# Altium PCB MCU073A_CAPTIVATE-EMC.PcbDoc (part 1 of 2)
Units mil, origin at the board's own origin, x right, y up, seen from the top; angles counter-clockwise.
Board outline 5374.02 x 3444.88 mil, 2 copper layers (Top Layer, Bottom Layer), stack 62 mil thick; 125 components, 86 nets, 448 pads, 154 vias.
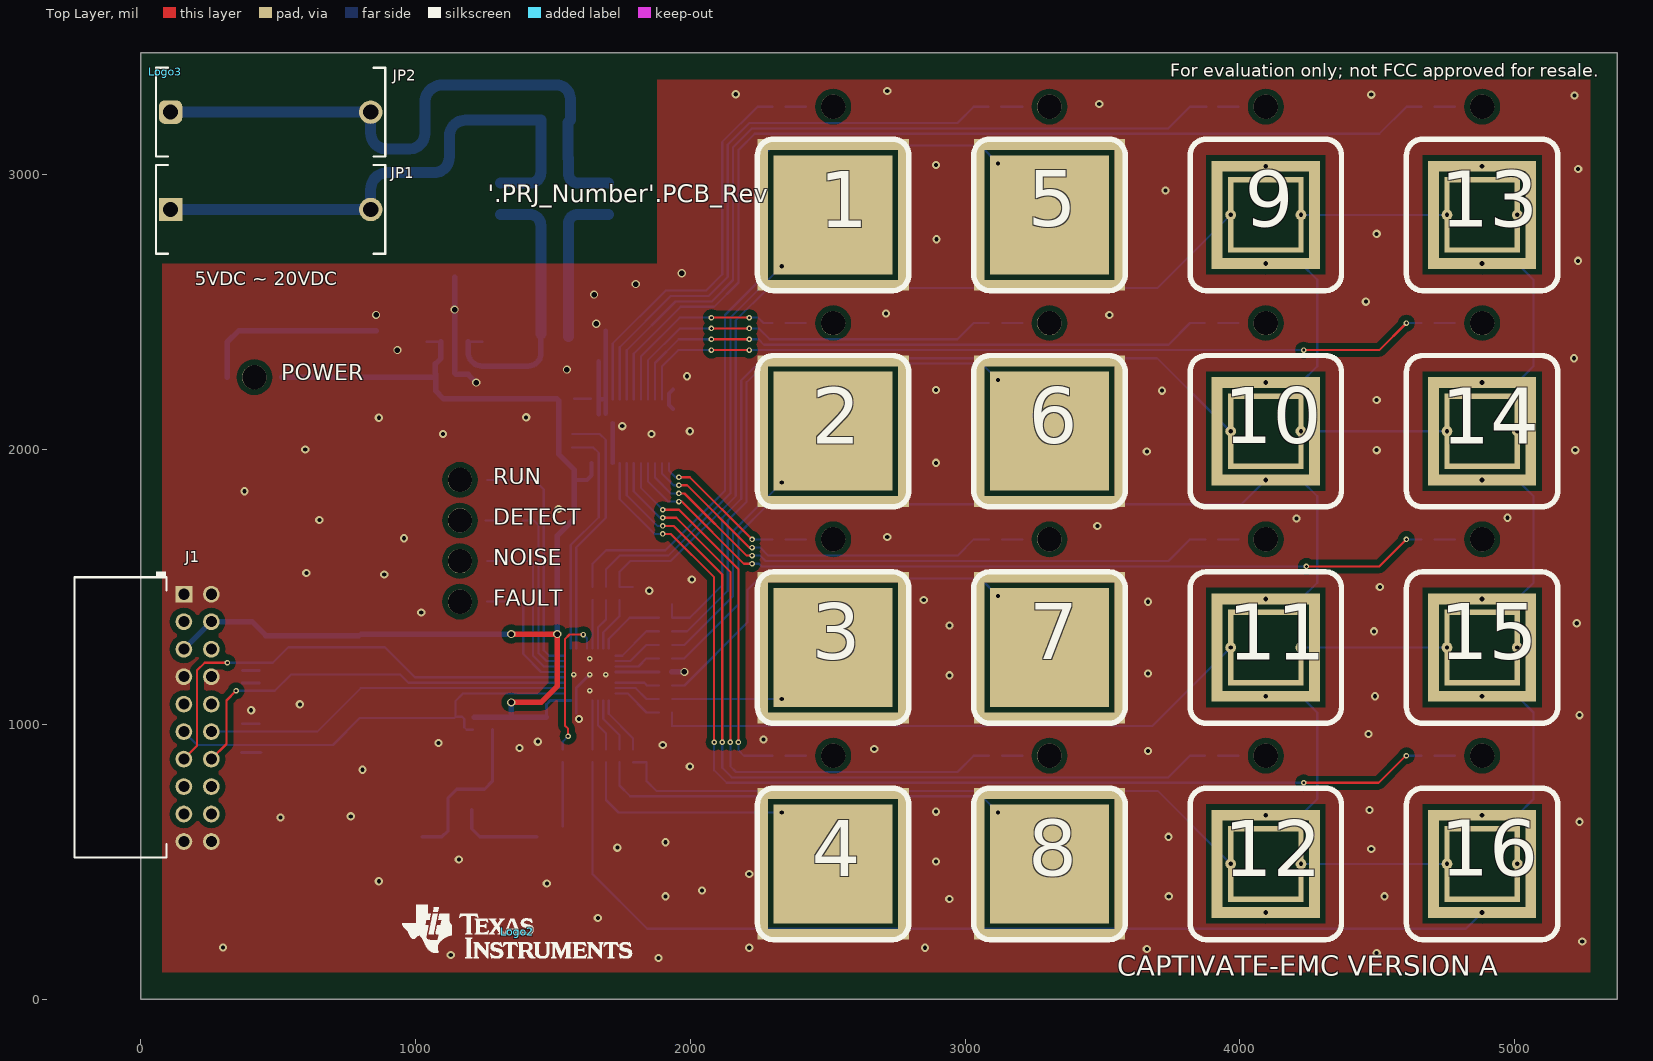
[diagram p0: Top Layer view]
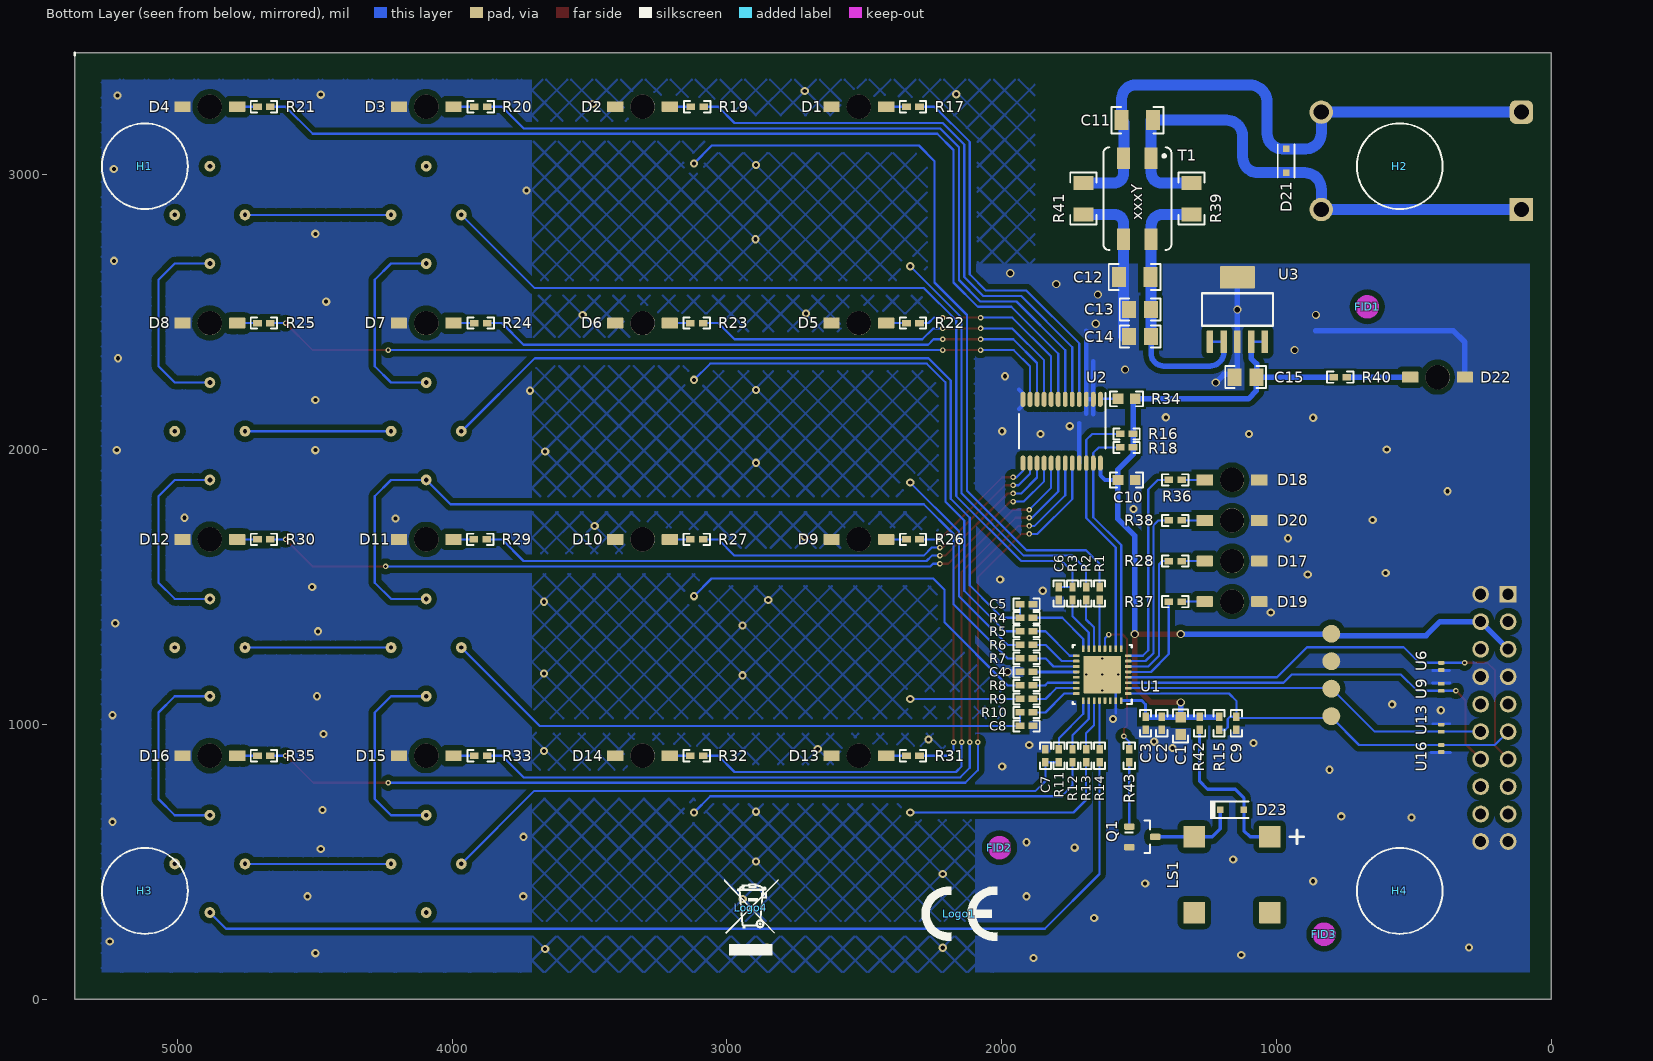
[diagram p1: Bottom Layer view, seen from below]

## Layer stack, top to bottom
Top Solder: solder mask 0.4, Solder Resist, Dk 3.5
Top Layer: signal copper 1.4
Dielectric1: core 59.2, FR-4, Dk 4.8
Bottom Layer: signal copper 1.4
Bottom Solder: solder mask 0.4, Solder Resist, Dk 3.5

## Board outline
0,0 0,3444.88 5374.02,3444.88 5374.02,0

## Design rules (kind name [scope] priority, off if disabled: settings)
AcuteAngle [All] p1: minimum=4.50000000000000E+0001 checktracksonly=FALSE
AssemblyTestPointUsage [All] p1: valid=2
BoardOutlineClearance BoardOutlineClearance_MountingHoles [OnCopper and InComponentClass('Mounting Holes')] p1: gap=39.37 ignorepadtopadclearanceinfootprint=FALSE
BoardOutlineClearance BoardOutlineClearance_Poly [OnCopper and IsPoly] p2: gap=25 ignorepadtopadclearanceinfootprint=FALSE
BoardOutlineClearance [OnCopper and Not InComponentClass('Logo') and not InComponentClass('FiducialMark') and not InRegion(1000,500,4000,800) and not InPoly] p3: gap=50 ignorepadtopadclearanceinfootprint=FALSE
Clearance Clearance_Keepouts [((IsTrack Or IsArc) And Not InPoly) And IsFree and IsKeepOut vs ((IsTrack Or IsArc) And Not InPoly) And IsFree and IsKeepOut] p1: gap=0 ignorepadtopadclearanceinfootprint=FALSE
Clearance Clearance_Poly [InPolygon] p2: gap=20 ignorepadtopadclearanceinfootprint=TRUE
Clearance Clearance_FiducialMark [IsKeepOut and InComponentClass('FiducialMark') vs IsPad and InComponentClass('FiducialMark')] p3: gap=0 ignorepadtopadclearanceinfootprint=FALSE
Clearance [All] p4: gap=7.87 ignorepadtopadclearanceinfootprint=TRUE
ComponentClearance ComponentClearance_MountingHoles_FiducialMarks [InComponentClass('Mounting Holes') vs InComponentClass('FiducialMark')] p1: gap=50 collisioncheckmode=3 verticalgap=10 showdistances=FALSE
ComponentClearance ComponentClearance_Overlay [HasFootprint('CAPTIVATE-EMC-OVERLAY-PMMA')] p2: gap=0 collisioncheckmode=3 verticalgap=0 showdistances=FALSE
ComponentClearance ComponentClearance_Shunt [InComponentClass('Header') vs InComponentClass('Shunt')] p3: gap=0 collisioncheckmode=3 verticalgap=0 showdistances=FALSE
ComponentClearance ComponentClearance_Logo [InComponentClass('Logo')] p4: gap=50 collisioncheckmode=3 verticalgap=10 showdistances=FALSE
ComponentClearance ComponentClearance_ScrewToNut [(HasFootprint('NY PMS 440 0025 PH')) vs (HasFootprint('Keystone_1902C'))] p5: gap=5 collisioncheckmode=3 verticalgap=10 showdistances=FALSE
ComponentClearance ComponentClearance_MountingHoles [InComponentClass('Mounting Holes')] p6: gap=250 collisioncheckmode=3 verticalgap=100000 showdistances=FALSE
ComponentClearance ComponentClearance_SmallPassives [HasFootprint('0201*') or HasFootprint('0402*') or HasFootprint('0508') or HasFootprint('0603*') or HasFootprint('0612') or HasFootprint('0805*') or HasFootprint('0815*') or HasFootprint('0830*') or HasFootprint('1206*') or HasFootprint('1210*') or HasFootprint('1808*') or HasFootprint('1812*') or HasFootprint('1825*') or HasFootprint('2010*') or HasFootprint('2220*') or HasFootprint('2225*') or HasFootprint('2512*') or HasFootprint('2728*') or HasFootprint('3518*') vs HasFootprint('0201*') or HasFootprint('0402*') or HasFootprint('0508') or HasFootprint('0603*') or HasFootprint('0612') or HasFootprint('0805*') or HasFootprint('0815*') or HasFootprint('0830*') or HasFootprint('1206*') or HasFootprint('1210*') or HasFootprint('1808*') or HasFootprint('1812*') or HasFootprint('1825*') or HasFootprint('2010*') or HasFootprint('2220*') or HasFootprint('2225*') or HasFootprint('2512*') or HasFootprint('2728*') or HasFootprint('3518*')] p7: gap=14.96 collisioncheckmode=3 verticalgap=10 showdistances=FALSE
ComponentClearance ComponentClearance_THtoSMT [IsThruComponent vs IsSMTComponent] p8: gap=40 collisioncheckmode=3 verticalgap=30 showdistances=FALSE
ComponentClearance ComponentClearance_THtoTH [IsThruComponent vs IsThruComponent] p9: gap=30 collisioncheckmode=3 verticalgap=30 showdistances=FALSE
ComponentClearance [All] p10: gap=30 collisioncheckmode=3 verticalgap=10 showdistances=FALSE
DiffPairsRouting [All] p1: maxlimit=100 minlimit=10 mostfreqgap=10 toplayer_minwidth=15 toplayer_maxwidth=15 toplayer_prefwidth=15 bottomlayer_minwidth=15 bottomlayer_maxwidth=15 bottomlayer_prefwidth=15 maxuncoupledlength=1000
FabricationTestPointUsage TestPointUsage [All] p1: valid=2 allowmultiple=FALSE
FabricationTestpoint Testpoint [All] p1: side=3 testpointundercomponent=TRUE minsize=40 maxsize=100 preferedsize=60 minholesize=0 maxholesize=40 preferedholesize=32 testpointgrid=1 allowsidetop=TRUE allowsidebottom=TRUE usegrid=TRUE gridtolerance=0.01
FanoutControl Fanout_LCC [IsLCC] p1: bgadir=Out bgaviamode=Centered fanoutstyle=Auto fanoutdirection=Alternating viagrid=1 // Fanout_LCC (Default Rule)
FanoutControl Fanout_BGA [IsBGA] p2: bgadir=Out bgaviamode=Centered fanoutstyle=Auto fanoutdirection=Alternating viagrid=1 // Fanout_BGA (Default Rule)
FanoutControl Fanout_Default [All] p4: bgadir=Out bgaviamode=Centered fanoutstyle=Auto fanoutdirection=Alternating viagrid=1 // Fanout_Default (Default Rule)
FanoutControl Fanout_Small [(CompPinCount < 5)] p5: bgadir=Out bgaviamode=Centered fanoutstyle=Auto fanoutdirection=OutThenIn viagrid=1 // Fanout_Small (Default Rule)
HoleSize [All] p1: absolutevalues=TRUE maxlimit=251 minlimit=7.87 maxpercent=80.000 minpercent=20.000
MinimumAnnularRing MinimumAnnularRing_ThermalPadVias [IsVia and InAnyComponent] p1: minimumring=5.91
MinimumAnnularRing [All] p2: minimumring=5
MinimumSolderMaskSliver MinimumSolderMaskSliver_Logo [InComponentClass('Logo') vs InComponentClass('Logo')] p1: minsoldermaskwidth=0.7
MinimumSolderMaskSliver [All] p2: minsoldermaskwidth=3.94
PlaneConnect [All] p1: planeconnectstyle=Direct reliefexpansion=10 reliefentries=4 reliefconductorwidth=10 reliefairgap=10
PolygonConnect [All] p1: connectstyle=Direct reliefconductorwidth=10 reliefentries=4 polygonreliefangle="90 Angle" airgapwidth=10
RoutingVias ThermalPadVias [IsVia and InAnyComponent] p1: holewidth=7.87 width=19.68 viastyle="Through Hole" minholewidth=7.87 minwidth=19.68 maxholewidth=12.99 maxwidth=23.62
RoutingVias [All] p2: holewidth=16 width=34 viastyle="Through Hole" minholewidth=7.87 minwidth=20 maxholewidth=40 maxwidth=65
SilkToBoardRegionClearance [Not ((IsComment or IsDesignator) And (Hide <> 'False')) and not InRegion(1000,500,4000,800)] p1:
SilkToSilkClearance SilkToSilkClearance_Pb-FreeLogo [(HasFootprint('Pb-Free_Overlay_Medium') OR HasFootprint('Pb-Free_Overlay_Small')) vs (HasFootprint('Pb-Free_Overlay_Medium') OR HasFootprint('Pb-Free_Overlay_Small'))] p1: silktosilkclearance=0
SilkToSilkClearance [All] p2: silktosilkclearance=3.94
SilkToSolderMaskClearance SilkToComponentPadClearance [(IsPad or IsFill or IsRegion) and InAnycomponent] p1: minsilkscreentomaskgap=5 clearancetoexposedcopper=TRUE
SilkToSolderMaskClearance "Silk to Solder Mask Opening" [All] p2: minsilkscreentomaskgap=3.94 clearancetoexposedcopper=FALSE
SolderMaskExpansion [All] p1: expansion=1.97
UnRoutedNet [All] p1: checkbadconnections=TRUE
Width [All] p1: maxlimit=100 minlimit=6 preferedwidth=10 checkconnectedcopper=TRUE
14 further rules are at their usual default settings.

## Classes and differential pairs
component class MCU073A_CAPTIVATE-EMC_PowerSupply: C11 C12 C13 C14 C15 D21 D22 J1 JP1 JP2 R39 R40 R41 T1 U3 U6 U9 U13 U16
component class MCU073A_CAPTIVATE-EMC_MCU: 1 2 3 4 5 6 7 8 9 10 11 12 13 14 15 16 C1 C2 C3 C4 C5 C6 C7 C8 C9 C10 D1 D2 D3 D4 D5 D6 D7 D8 D9 D10 D11 D12 D13 D14 D15 D16 D17 D18 D19 D20 D23 LS1 Q1 R1 R2 R3 R4 R5 R6 R7 R8 R9 R10 R11 R12 R13 R14 R15 R16 R17 R18 R19 R20 R21 R22 R23 R24 R25 R26 R27 R28 R29 R30 R31 R32 R33 R34 R35 R36 R37 R38 R42 R43 U1 U2
component class AssemblyNote: ZZ1 ZZ2 ZZ3 ZZ4
component class FiducialMark: FID1 FID2 FID3
component class MCU073A_CAPTIVATE-EMC_Hardware: FID1 FID2 FID3 H1 H2 H3 H4 Logo1 Logo2 Logo3 Logo4 ZZ1 ZZ2 ZZ3 ZZ4
component class Logo: Logo2

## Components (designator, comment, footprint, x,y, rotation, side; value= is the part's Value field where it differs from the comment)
1 "Btn-Self" btn-self 2519.68,2854.33 r90 top
2 "Btn-Self" btn-self 2519.68,2066.93 r90 top
3 "Btn-Self" btn-self 2519.68,1279.53 r90 top
4 "Btn-Self" btn-self 2519.68,492.13 r90 top
5 "Btn-Self" btn-self 3307.09,2854.33 r90 top
6 "Btn-Self" btn-self 3307.09,2066.93 r90 top
7 "Btn-Self" btn-self 3307.09,1279.53 r90 top
8 "Btn-Self" btn-self 3307.09,492.13 r90 top
9 "Btn-Mutual" btn-mutual 4094.49,2854.33 r270 top
10 "Btn-Mutual" btn-mutual 4094.49,2066.93 r90 top
11 "Btn-Mutual" btn-mutual 4094.49,1279.53 r90 top
12 "Btn-Mutual" btn-mutual 4094.49,492.13 r90 top
13 "Btn-Mutual" btn-mutual 4881.89,2854.33 r90 top
14 "Btn-Mutual" btn-mutual 4881.89,2066.93 r90 top
15 "Btn-Mutual" btn-mutual 4881.89,1279.53 r90 top
16 "Btn-Mutual" btn-mutual 4881.89,492.13 r90 top
C1 "GRM188R60J106ME47D" 0603 1348.42,994.09 r270 bottom value=10uF
C2 "C1005X5R0J475M050BC" 0402 1417.32,1003.94 r270 bottom value=4.7uF
C3 "GCM155R71C104KA55D" 0402 1476.38,1003.94 r90 bottom value=0.1uF
C4 "GRM155R70J105KA12D" 0402 1909.45,1190.94 r0 bottom value=1uF
C5 "C0402C101J3GACTU" 0402 1909.45,1437.01 r0 bottom value=100pF
C6 "C0402C101J3GACTU" 0402 1791.34,1476.38 r90 bottom value=100pF
C7 "C0402C101J3GACTU" 0402 1840.55,885.83 r270 bottom value=100pF
C8 "C0402C101J3GACTU" 0402 1909.45,994.09 r0 bottom value=100pF
C9 "GCM155R71H102KA37D" 0402 1145.67,1003.94 r90 bottom value=1000pF
C10 "GCJ188R72A104KA01D" 0603 1545.28,1889.76 r180 bottom value=0.1uF
C11 "12061C104MAT2A" 1206 1505.91,3198.82 r180 bottom value=0.1uF
C12 "12063C105KAT2A" 1206 1515.75,2627.95 r0 bottom value=1uF
C13 "CL21A106KAFN3NE" 0805_HV 1496.06,2509.84 r0 bottom value=10uF
C14 "08053C104KAT2A" 0805_HV 1496.06,2411.42 r0 bottom value=0.1uF
C15 "CL21A106KAFN3NE" 0805_HV 1112.2,2263.78 r0 bottom value=10uF
D1 "AM2520SRC09" FP-AM2520SRC09_SMD2-MFG 2519.68,3248.03 r180 bottom
D2 "AM2520SRC09" FP-AM2520SRC09_SMD2-MFG 3307.09,3248.03 r180 bottom
D3 "AM2520SRC09" FP-AM2520SRC09_SMD2-MFG 4094.49,3248.03 r180 bottom
D4 "AM2520SRC09" FP-AM2520SRC09_SMD2-MFG 4881.89,3248.03 r180 bottom
D5 "AM2520SRC09" FP-AM2520SRC09_SMD2-MFG 2519.68,2460.63 r180 bottom
D6 "AM2520SRC09" FP-AM2520SRC09_SMD2-MFG 3307.09,2460.63 r180 bottom
D7 "AM2520SRC09" FP-AM2520SRC09_SMD2-MFG 4094.49,2460.63 r180 bottom
D8 "AM2520SRC09" FP-AM2520SRC09_SMD2-MFG 4881.89,2460.63 r180 bottom
D9 "AM2520SRC09" FP-AM2520SRC09_SMD2-MFG 2519.68,1673.23 r180 bottom
D10 "AM2520SRC09" FP-AM2520SRC09_SMD2-MFG 3307.09,1673.23 r180 bottom
D11 "AM2520SRC09" FP-AM2520SRC09_SMD2-MFG 4094.49,1673.23 r180 bottom
D12 "AM2520SRC09" FP-AM2520SRC09_SMD2-MFG 4881.89,1673.23 r180 bottom
D13 "AM2520SRC09" FP-AM2520SRC09_SMD2-MFG 2519.68,885.83 r180 bottom
D14 "AM2520SRC09" FP-AM2520SRC09_SMD2-MFG 3307.09,885.83 r180 bottom
D15 "AM2520SRC09" FP-AM2520SRC09_SMD2-MFG 4094.49,885.83 r180 bottom
D16 "AM2520SRC09" FP-AM2520SRC09_SMD2-MFG 4881.89,885.83 r180 bottom
D17 "AM2520SECK09" FP-AM2520SECK09_SMT_LED_2MM5_2MM0-MFG 1161.42,1594.49 r0 bottom
D18 "AM2520ZGC09" FP-AM2520ZGC09_SMD2-0 1167.32,1889.76 r0 bottom
D19 "AM2520SRC09" FP-AM2520SRC09_SMD2-MFG 1161.42,1446.85 r0 bottom
D20 "AM2520QBC/D09" FP-AM2520QBC_D09 1161.42,1742.13 r0 bottom
D21 "CDSOD323-T15SC" SOD-323-Bi 964.57,3051.18 r270 bottom value=15V
D22 "AM2520SRC09" FP-AM2520SRC09_SMD2-MFG 413.39,2263.78 r0 bottom
D23 "1N4148WX-TP" SOD-323 1161.42,688.98 r180 bottom value=75V
FID1 "Fiducial" Fiducial10-20 669.29,2519.68 r180 bottom
FID2 "Fiducial" Fiducial10-20 2007.87,551.18 r180 bottom
FID3 "Fiducial" Fiducial10-20 826.77,236.22 r180 bottom
H1 "SJ61A1" Bumpon_SJ61A1 5118.11,3031.5 r90 bottom
H2 "SJ61A1" Bumpon_SJ61A1 551.18,3031.5 r90 bottom
H3 "SJ61A1" Bumpon_SJ61A1 5118.11,393.7 r90 bottom
H4 "SJ61A1" Bumpon_SJ61A1 551.18,393.7 r90 bottom
J1 "PPPC102LJBN-RC" Sullins_xPxC102LJBN 206.63,1023.62 r180 top
JP1 "973 582-101" "HIRSCHMANN_973 582-101" 472.44,2874.02 r0 top
JP2 "973 582-100" "HIRSCHMANN_973 582-100" 472.44,3228.35 r0 top
Logo1 "CE Mark" CE_Mark_5mm 2153.54,311.02 r180 bottom
Logo2 "Texas Instruments" TI_Stacked_Overlay_Small 1369.68,246.06 r0 top
Logo3 "FCC disclaimer" FCC_disclaimer 88.58,3375.98 r0 top
Logo4 "WEEE logo" WEEE_Minimum 2913.39,332.02 r180 bottom
LS1 "ST-03BL" Soberton_ST-03BL 1161.42,452.76 r270 bottom
Q1 "MMBT3904-7-F" SOT-23 1488.19,590.55 r180 bottom value="40 V"
R1 "CRCW04022K00JNED" 0402 1643.7,1476.38 r90 bottom value=2.0k
R2 "CRCW04022K00JNED" 0402 1692.91,1476.38 r90 bottom value=2.0k
R3 "CRCW04022K00JNED" 0402 1742.13,1476.38 r90 bottom value=2.0k
R4 "CRCW04022K00JNED" 0402 1909.45,1387.79 r0 bottom value=2.0k
R5 "CRCW04022K00JNED" 0402 1909.45,1338.58 r0 bottom value=2.0k
R6 "CRCW04022K00JNED" 0402 1909.45,1289.37 r0 bottom value=2.0k
R7 "CRCW04022K00JNED" 0402 1909.45,1240.16 r0 bottom value=2.0k
R8 "CRCW04022K00JNED" 0402 1909.45,1141.73 r0 bottom value=2.0k
R9 "CRCW04022K00JNED" 0402 1909.45,1092.52 r0 bottom value=2.0k
R10 "CRCW04022K00JNED" 0402 1909.45,1043.31 r0 bottom value=2.0k
R11 "CRCW04022K00JNED" 0402 1791.34,885.83 r270 bottom value=2.0k
R12 "CRCW04022K00JNED" 0402 1742.13,885.83 r270 bottom value=2.0k
R13 "CRCW04022K00JNED" 0402 1692.91,885.83 r270 bottom value=2.0k
R14 "CRCW04022K00JNED" 0402 1643.7,885.83 r270 bottom value=2.0k
R15 "CRCW040247K0JNED" 0402 1208.66,1003.94 r90 bottom value=47k
R16 "CRCW04022K20JNED" 0402 1545.28,2057.09 r180 bottom value=2.2k
R17 "CRCW04021K00JNED" 0402 2322.83,3248.03 r0 bottom value=1.0k
R18 "CRCW04022K20JNED" 0402 1545.28,2007.87 r180 bottom value=2.2k
R19 "CRCW04021K00JNED" 0402 3108.27,3248.03 r0 bottom value=1.0k
R20 "CRCW04021K00JNED" 0402 3896.42,3248.03 r0 bottom value=1.0k
R21 "CRCW04021K00JNED" 0402 4685.04,3248.03 r0 bottom value=1.0k
R22 "CRCW04021K00JNED" 0402 2322.83,2460.63 r0 bottom value=1.0k
R23 "CRCW04021K00JNED" 0402 3110.24,2460.63 r0 bottom value=1.0k
R24 "CRCW04021K00JNED" 0402 3896.42,2460.63 r0 bottom value=1.0k
R25 "CRCW04021K00JNED" 0402 4685.04,2460.63 r0 bottom value=1.0k
R26 "CRCW04021K00JNED" 0402 2322.64,1673.23 r0 bottom value=1.0k
R27 "CRCW04021K00JNED" 0402 3110.24,1673.23 r0 bottom value=1.0k
R28 "CRCW04021K00JNED" 0402 1368.11,1594.49 r180 bottom value=1.0k
R29 "CRCW04021K00JNED" 0402 3897.64,1673.23 r0 bottom value=1.0k
R30 "CRCW04021K00JNED" 0402 4685.04,1673.23 r0 bottom value=1.0k
R31 "CRCW04021K00JNED" 0402 2322.83,885.83 r0 bottom value=1.0k
R32 "CRCW04021K00JNED" 0402 3110.24,885.83 r0 bottom value=1.0k
R33 "CRCW04021K00JNED" 0402 3896.42,885.83 r0 bottom value=1.0k
R34 "RC1608J103CS" 0603 1545.28,2185.04 r0 bottom value=10k
R35 "CRCW04021K00JNED" 0402 4685.04,885.83 r0 bottom value=1.0k
R36 "CRCW04021K00JNED" 0402 1368.11,1889.76 r180 bottom value=1.0k
R37 "CRCW04021K00JNED" 0402 1368.11,1446.85 r180 bottom value=1.0k
R38 "CRCW04021K00JNED" 0402 1368.11,1742.13 r180 bottom value=1.0k
R39 "MCR18EZHJ000" 1206 1309.05,2913.39 r270 bottom value=0
R40 "CRCW04021K00JNED" 0402 767.72,2263.78 r0 bottom value=1.0k
R41 "MCR18EZHJ000" 1206 1702.76,2913.39 r270 bottom value=0
R42 "CRCW040251R0JNED" 0402 1279.53,1003.94 r90 bottom value=51
R43 "CRCW0402180RJNED" 0402 1535.43,885.83 r270 bottom value=180
T1 "SRF0905-472Y" SRF0905 1505.91,2913.39 r270 bottom value=4.7mH
U1 "MSP430FR2676TRHB" RHB0032E 1633.86,1181.1 r0 bottom
U2 "TCA9535PWR" PW0024A_N 1781.5,2066.93 r270 bottom
U3 "TPS7A4533DCQR" DCQ0006A_N 1141.73,2509.84 r90 bottom
U6 "TPD1E10B06DPYT" DPY0002A 400,1211 r90 bottom
U9 "TPD1E10B06DPYT" DPY0002A 400,1135 r270 bottom
U13 "TPD1E10B06DPYT" DPY0002A 400,986 r270 bottom
U16 "TPD1E10B06DPYT" DPY0002A 400,912 r90 bottom
ZZ1 "These assemblies are ESD sensitive, ESD precautions shall be observed." AssemblyNote 126.97,5085.53 r0 top
ZZ2 "These assemblies must be clean and free from flux and all contaminants. Use of no clean flux is not acceptable." AssemblyNote 126.97,4940.4 r0 top
ZZ3 "These assemblies must comply with workmanship standards IPC-A-610 Class 2, unless otherwise specified." AssemblyNote 126.97,4795.28 r0 top
ZZ4 "Overlay Assembly Notes / Component 'M1' represents the keypad overlay dielectric assembly. / The adhesive shall be cut to the same pattern as the plastic, and attached to the back of the plastic.  Then, the overlay plastic shall be bonded to the top layer of the PCB." AssemblyNote 128.94,4621.06 r0 top

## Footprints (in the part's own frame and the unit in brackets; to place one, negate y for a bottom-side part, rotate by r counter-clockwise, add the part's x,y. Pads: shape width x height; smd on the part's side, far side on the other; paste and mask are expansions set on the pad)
0402 [mm] "0402 from SM-752 data"
  rect 0.8x0.6 smd: 1(-0.6,0) 2(0.6,0)
  silkscreen extent -1.22,-0.52 1.22,0.52, body extent -0.55,-0.3 0.55,0.3, height 0.6
0603 [mm] "0603 from SM-752 data"
  rect 1x0.95 smd: 1(-0.8,0) 2(0.8,0)
  silkscreen extent -1.52,-0.69 1.52,0.69, body extent -0.87,-0.47 0.87,0.47, height 1
0805_HV [mil] "0805 with 30mil clearance between pads"
  rect 50x63 smd: 1(-40,0) 2(40,0)
  silkscreen extent -74,-40 74,40, body extent -43,-29 43,29, height 57
1206 [mm] "1206 from SM-752 data"
  rect 1.3x1.85 smd: 1(-1.45,0) 2(1.45,0)
  silkscreen extent -2.4,-1.21 2.4,1.21, body extent -1.7,-0.9 1.7,0.9, height 1.35
AssemblyNote [mil] "Assembly Note"
btn-mutual [mm] "Mutual Capacitance Button"
  rect 0.5x7 smd paste+0: RX(-3.25,0) RX(3.25,0)
  round 1 hole 0.4: RX(0,3.25) RX(0,-3.25)
  rect 7x0.5 smd paste+0: RX(0,3.25) RX(0,-3.25)
  round 1 hole 0.45: TX(-4.5,0) TX(4.5,0)
  rect 1x10 smd paste+0: TX(-4.5,0) TX(4.5,0)
  rect 10x1 smd paste+0: TX(0,4.5) TX(0,-4.5)
  Top Layer pour cut-out: -5.2,5.2 5.2,5.2 5.2,-5.2 -5.2,-5.2
  silkscreen extent -7,-7 7,7
btn-self [mm] "Self Capacitance Button"
  rect 1x14 smd paste+0: GND(-6.5,0)
  rect 14x1 smd paste+0 mask+0: GND(0,6.5) GND(0,-6.5)
  rect 1x14 smd paste+0 mask+0: GND(6.5,0)
  rect 11x11 smd paste+0: RX(0,0)
  silkscreen extent -7,-7 7,7
Bumpon_SJ61A1 [mil] "3M Cylindrical Bumpon black"
  round 1 on Mech4: 0(0,0)
  silkscreen extent -156,-156 156,156, body extent -156,-156 156,156, height 201
CE_Mark_5mm [mil] "Minimum text height for CE Mark"
  silkscreen extent -138,-98 138,98
DCQ0006A_N [mm] "SOT223, 6-Leads, Body 6.6x7.3mm (max), Pitch 1.27mm, IPC Medium Density"
  rrect17% 2.1x0.6 smd: 1(-2.975,2.54) 2(-2.975,1.27) 3(-2.975,0) 4(-2.975,-1.27) 5(-2.975,-2.54)
  rrect5% 2.1x3.2 smd: 6(2.975,0)
  silkscreen extent -1.5,-3.27 1.5,3.27, body extent -3.54,-3.25 3.54,3.25, height 1.8
DPY0002A [mm] "X1SON-2"
  rrect57% 0.35x0.6 smd paste-0.5 mask-0.05: 1(-0.325,0) 2(0.325,0)
  rrect33% 0.3x0.5 on Bottom Paste: 1S(-0.35,0) 2S(0.35,0)
  body extent -0.5,-0.3 0.5,0.3, height 0.45
FCC_disclaimer [mil]
Fiducial10-20 [mm]
  round 1 smd mask+0.5: 1(0,0)
  Top Layer keep-out circle w1.178: c0,0 r0.5
FP-AM2520QBC_D09 [mm]
  rect 1.5x1 smd paste+0 mask+0: 1(-2.525,0) 2(2.525,0)
  round 2.25 hole 2.25 unplated paste-1000 mask+0: ""(0,0)
  body extent -2.98,-1 2.82,1, height 1.7
FP-AM2520SECK09_SMT_LED_2MM5_2MM0-MFG [mm]
  rrect10% 1.5x1 smd paste+0 mask+0: 1(-2.525,0) 2(2.525,0)
  round 2.25 hole 2.25 unplated paste-1000 mask+0: ""(0,0)
  body extent -2.9,-1 2.9,1, height 1.4
FP-AM2520SRC09_SMD2-MFG [mm]
  rrect10% 1.5x1 smd paste+0 mask+0: 1(-2.525,0) 2(2.525,0)
  round 2.25 hole 2.25 unplated paste-1000 mask+0: ""(0,0)
  body extent -2.9,-1 2.9,1, height 1.5
FP-AM2520ZGC09_SMD2-0 [mm]
  rect 1.5x1 smd paste+0 mask+0: 1(-2.675,0) 2(2.375,0)
  round 2.25 hole 2.25 unplated paste-1000 mask+0: ""(-0.15,0)
  body extent -3.13,-1 2.67,1, height 1.7
"HIRSCHMANN_973 582-100" [mil] "Hirschmann Automation and Control GmbH"
  rrect50% 85x85 hole 55: 1(-364.17,0)
  round 85 hole 55: 2(364.17,0)
  silkscreen extent -417,-161 417,161, body extent -414,-157 413,157, height 413
"HIRSCHMANN_973 582-101" [mil] "Hirschmann Automation and Control GmbH"
  rect 85x85 hole 55: 1(-364.17,0)
  round 85 hole 55: 2(364.17,0)
  silkscreen extent -417,-161 417,161, body extent -414,-157 413,157, height 413
PW0024A_N [mm] "TSOP, 24-Leads, Body 7.8x4.4mm, Pitch 0.65mm, IPC Medium Density"
  oval 1.4x0.45 smd: 1(-2.95,3.575) 2(-2.95,2.925) 3(-2.95,2.275) 4(-2.95,1.625) 5(-2.95,0.975) 6(-2.95,0.325) 7(-2.95,-0.325) 8(-2.95,-0.975) 9(-2.95,-1.625) 10(-2.95,-2.275) 11(-2.95,-2.925) 12(-2.95,-3.575) 13(2.95,-3.575) 14(2.95,-2.925) 15(2.95,-2.275) 16(2.95,-1.625) 17(2.95,-0.975) 18(2.95,-0.325) 19(2.95,0.325) 20(2.95,0.975) 21(2.95,1.625) 22(2.95,2.275) 23(2.95,2.925) 24(2.95,3.575)
  silkscreen extent -3.51,-3.95 1.6,4.04, body extent -3.21,-3.9 3.21,3.9, height 1
RHB0032E [mm] "QFN, 32-Leads, Body 5x5mm, Pitch 0.5mm, Thermal Pad 3.45x3.45mm, TI Recommended"
  rrect40% 0.6x0.25 smd: 1(-2.4,1.75) 2(-2.4,1.25) 3(-2.4,0.75) 4(-2.4,0.25) 5(-2.4,-0.25) 6(-2.4,-0.75) 7(-2.4,-1.25) 8(-2.4,-1.75) 17(2.4,-1.75) 18(2.4,-1.25) 19(2.4,-0.75) 20(2.4,-0.25) 21(2.4,0.25) 22(2.4,0.75) 23(2.4,1.25) 24(2.4,1.75)
  rrect40% 0.25x0.6 smd: 9(-1.75,-2.4) 10(-1.25,-2.4) 11(-0.75,-2.4) 12(-0.25,-2.4) 13(0.25,-2.4) 14(0.75,-2.4) 15(1.25,-2.4) 16(1.75,-2.4) 25(1.75,2.4) 26(1.25,2.4) 27(0.75,2.4) 28(0.25,2.4) 29(-0.25,2.4) 30(-0.75,2.4) 31(-1.25,2.4) 32(-1.75,2.4)
  rrect3% 3.45x3.45 smd paste-1.725: 33(0,0)
  rrect7% 1.49x1.49 on Bottom Paste: ""(-0.845,-0.845) ""(-0.845,0.845) ""(0.845,-0.845) ""(0.845,0.845)
  silkscreen extent -2.72,-2.73 2.72,2.73, body extent -2.57,-2.57 2.58,2.58, height 1.01
Soberton_ST-03BL [mm] "SMD, 4-Leads, Body 8.5x8.5mm"
  rrect5% 2x2 smd: 1(-3.5,3.5) 2(-3.5,-3.5) 3(3.5,-3.5) 4(3.5,3.5)
  body extent -4.2,-4.2 4.2,4.2, height 2.9
SOD-323 [mm] "NXP recommended land pattern"
  rect 0.6x0.6 smd paste-0.05: 1(-1.1,0) 2(1.1,0)
  silkscreen extent -2.06,-0.86 1.53,0.86, body extent -1.3,-0.67 1.3,0.68, height 1.1
SOD-323-Bi [mm] "SOD323, 2-Leads, Body 1.9x1.45mm, No Polarity Mark"
  rect 0.6x0.6 smd paste-0.05: 1(-1.1,0) 2(1.1,0)
  silkscreen extent -1.53,-0.77 1.53,0.77, body extent -1.27,-0.65 1.27,0.65, height 1.02
SOT-23 [mm] "SOT23, 3-Leads, Body 2.9x1.3mm, Pitch 0.95mm, Lead Span 2.5mm, IPC Medium Density"
  rrect50% 1x0.6 smd: 1(-1.2,0.95) 2(-1.2,-0.95) 3(1.2,0)
  silkscreen extent -1.63,-1.5 0.7,1.5, body extent -1.16,-1.45 1.21,1.45, height 1
SRF0905 [mm] "Bourns SRF0905 series recommended land pattern"
  rect 2x1.2 smd: 1(-3.75,1.27) 2(-3.75,-1.27) 3(3.75,-1.27) 4(3.75,1.27)
  silkscreen extent -4.75,-3.15 4.75,3.15, body extent -4.75,-3.15 4.75,3.15, height 5.3
Sullins_xPxC102LJBN [mm] "Receptacle, 2.54mm, 10x2, R/A, TH"
  rect 1.55x1.55 hole 1.02: 1(1.27,-11.43)
  round 1.55 hole 1.02: 2(-1.27,-11.43) 3(1.27,-8.89) 4(-1.27,-8.89) 5(1.27,-6.35) 6(-1.27,-6.35) 7(1.27,-3.81) 8(-1.27,-3.81) 9(1.27,-1.27) 10(-1.27,-1.27) 11(1.27,1.27) 12(-1.27,1.27) 13(1.27,3.81) 14(-1.27,3.81) 15(1.27,6.35) 16(-1.27,6.35) 17(1.27,8.89) 18(-1.27,8.89) 19(1.27,11.43) 20(-1.27,11.43)
  silkscreen extent 2.87,-13.55 11.37,12.9, body extent -1.41,-12.95 11.43,12.95, height 5.08
TI_Stacked_Overlay_Small [mil]
  silkscreen extent -418,-98 418,98
WEEE_Minimum [mil] "WEEElie bin"
  silkscreen extent -95,-172 99,104

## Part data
1 2 3 4 5 6 7 8: library part btn-self, "Capacitive Button, Self Capacitance, 2-Layer, EMC", Alternate Manufacturer=-, Manufacturer=N/A
9 10 11 12 13 14 15 16: library part btn-mutual, "Capacitive Button, Mutual Capacitance, 2-layer", Alternate Manufacturer=-, Manufacturer=N/A
C1: library part CMP-0007303-5, "CAP, CERM, 10 uF, 6.3 V, +/- 20%, X5R, 0603", Cap_Case=0603, Manufacturer=MuRata, Supplier Part Number 1=490-3896-1-ND, TempCo=X5R, Tolerance_%=20%, Value1="0.009 ohm", Value2=6.3V, ValueDisplayed=10uF
C2: library part CMP-0006258-2, "CAP, CERM, 4.7 uF, 6.3 V, +/- 20%, X5R, 0402", Cap_Case=0402, Manufacturer=TDK, Supplier Part Number 1=445-7395-1-ND, TempCo=X5R, Tolerance_%=20%, Value1=Unknown, Value2=6.3V, ValueDisplayed=4.7uF
C3: library part CMP-0006351-2, "CAP, CERM, 0.1 uF, 16 V, +/- 10%, X7R, 0402", Cap_Case=0402, Manufacturer=MuRata, Supplier Part Number 1=490-4759-2-ND, TempCo=X7R, Tolerance_%=10%, Value1=Unknown, Value2=16V, ValueDisplayed=0.1uF
C4: library part CMP-0064947-2, "CAP, CERM, 1 uF, 6.3 V,+/- 10%, X7R, 0402", Cap_Case=0402, Manufacturer=MuRata, Supplier Part Number 1=490-10024-1-ND, TempCo=X7R, Tolerance_%=10%, Value1=Unknown, Value2=6.3V, ValueDisplayed=1uF
C5 C6 C7 C8: library part CMP-0006233-2, "CAP, CERM, 100 pF, 25 V, +/- 5%, C0G/NP0, 0402", Cap_Case=0402, Manufacturer=Kemet, Supplier Part Number 1=399-1022-1-ND, TempCo=C0G/NP0, Tolerance_%=5%, Value1=Unknown, Value2=25V, ValueDisplayed=100pF
C9: library part CMP-0006354-2, "CAP, CERM, 1000 pF, 50 V, +/- 10%, X7R, AEC-Q200 Grade 1, 0402", Cap_Case=0402, Manufacturer=MuRata, Supplier Part Number 1=490-4761-1-ND, TempCo=X7R, Tolerance_%=10%, Value1=Unknown, Value2=50V, ValueDisplayed=1000pF
C10: library part CMP-0064935-4, "CAP, CERM, 0.1 uF, 100 V,+/- 10%, X7R, AEC-Q200 Grade 1, 0603", Cap_Case=0603, Manufacturer=MuRata, Supplier Part Number 1=490-13420-1-ND, TempCo=X7R, Tolerance_%=10%, Value1=Unknown, Value2=100V, ValueDisplayed=0.1uF
C11: library part CMP-0008489-2, "CAP, CERM, 0.1 uF, 100 V, +/- 20%, X7R, 1206", Cap_Case=1206, Manufacturer=AVX, Supplier Part Number 1=478-3786-1-ND, TempCo=X7R, Tolerance_%=20%, Value1="0.037 ohm", Value2=100V, ValueDisplayed=0.1uF
C12: library part CMP-0008509-2, "CAP, CERM, 1 uF, 25 V, +/- 10%, X7R, 1206", Cap_Case=1206, Manufacturer=AVX, Supplier Part Number 1=478-1567-1-ND, TempCo=X7R, Tolerance_%=10%, Value1="0.013 ohm", Value2=25V, ValueDisplayed=1uF
C13 C15: library part CMP-0007987-2, "CAP, CERM, 10 uF, 25 V, +/- 10%, X5R, 0805", Cap_Case=0805, Manufacturer="Samsung Electro-Mechanics", TempCo=X5R, Tolerance_%=10%, Value1=Unknown, Value2=25V, ValueDisplayed=10uF
C14: library part CMP-0007567-2, "CAP, CERM, 0.1 uF, 25 V, +/- 10%, X7R, 0805", Cap_Case=0805, Manufacturer=AVX, Supplier Part Number 1=478-3755-1-ND, TempCo=X7R, Tolerance_%=10%, Value1="0.28 ohm", Value2=25V, ValueDisplayed=0.1uF
D1 D2 D3 D4 D5 D6 D7 D8 D9 D10 D11 D12 D13 D14 D15 D16 D19 D22: library part CMP-0086387-1, "Red 2.5 x 2 x 2.8 mm 20° Clear 800 mcd 1.85 V Subminiature Solid State LED SMT", Color=Red, Manufacturer="Kingbright Company LLC", Power_TotalModule=75mW
D17: library part CMP-0086381-1, "SUBMINIATURE SOLID STATE LAMP, Super Bright Orange, 20o, 2700mcd Clear", Color=Orange, Manufacturer=Kingbright, Power_TotalModule=75mW
D18: library part CMP-0087006-1, "Green 2.5 x 2 x 2.8 mm 20° Clear 2700 mcd 3.3 V Subminiature Solid State LED SMT", Color=Green, Manufacturer=Kingbright, Power_TotalModule=102.5mW
D20: library part CMP-0077505-2, "LED Blue 465nm - Discrete 3.3V 2-SMD, Z-Bend", Color=Blue, Manufacturer=Kingbright, Power_TotalModule=120mW
D21: library part CMP-0006059-3, "Diode, TVS, Bi, 15 V, SOD323, 2-Leads, Body 1.9x1.45mm, No Polarity Mark", Manufacturer=Bourns, Value1=400W
D23: library part CMP-0082069-2, "Diode, Switching, 75 V, 0.15 A, SOD-323", Manufacturer="Micro Commercial Components", Value1=0.15A, Value2=1V
FID1 FID2 FID3: library part CMP-0077181-1, "Fiducial mark.  There is nothing to buy or mount.", Manufacturer=N/A
H1 H2 H3 H4: library part CMP-0003621-1, "Bumpon, Cylindrical, 0.312 X 0.200, Black", Manufacturer=3M, Supplier Part Number 1=SJ5746-0-ND
J1: library part CMP-0054680-1, "Receptacle, 2.54mm, 10x2, Gold, R/A, TH", Color=Black, Current_A=3A, Manufacturer="Sullins Connector Solutions", Supplier Part Number 1=S5563-ND, Voltage_V=250V
JP1: library part CMP-0055403-2, "TEST SOCKET, PCB, 4MM, RED", Manufacturer=Hirschmann, Supplier Part Number 1=06WX5875
JP2: library part CMP-0055402-3, "TEST SOCKET, PCB, 4MM, BLACK", Color=Black, Manufacturer=Hirschmann, Supplier Part Number 1=06WX5874
Logo1: library part CMP-0074844-1
Logo2: library part CMP-0074838-1, "Texas Instrument Corporate Signature"
Logo3: library part CMP-0074847-1, "FCC_disclaimer"
Logo4: library part CMP-0074769-1
LS1: library part CMP-0078858-2, "Magnetic Transducer, SMD", Manufacturer=Sobertron
Q1: library part CMP-0000387-2, "Transistor, NPN, 40 V, 0.2 A, SOT-23", Manufacturer="Diodes Inc.", Supplier Part Number 1=MMBT3904-FDICT-ND, Value1="0.2 A", Value2=400
R1 R2 R3 R4 R5 R6 R7 R8 R9 R10 R11 R12 R13 R14: library part CMP-0026889-5, "RES, 2.0 k, 5%, 0.063 W, AEC-Q200 Grade 0, 0402", Manufacturer=Vishay-Dale, Power_W=63mW, Supplier Part Number 1=541-2.0KJCT-ND, TempCo="200 ppm/C", Tolerance_%=5%, Value2=0.063W, Value_Code=2k00, ValueDisplayed=2.0k
R15: library part CMP-0026935-3, "RES, 47 k, 5%, 0.063 W, AEC-Q200 Grade 0, 0402", Manufacturer=Vishay-Dale, Power_W=63mW, Supplier Part Number 1=541-47KJCT-ND, TempCo="200 ppm/C", Tolerance_%=5%, Value2=0.063W, Value_Code=47k0, ValueDisplayed=47k
R16 R18: library part CMP-0026890-5, "RES, 2.2 k, 5%, 0.063 W, AEC-Q200 Grade 0, 0402", Manufacturer=Vishay-Dale, Power_W=63mW, Supplier Part Number 1=541-2.2KJCT-ND, TempCo="200 ppm/C", Tolerance_%=5%, Value2=0.063W, Value_Code=2k20, ValueDisplayed=2.2k
R17 R19 R20 R21 R22 R23 R24 R25 R26 R27 R28 R29 R30 R31 R32 R33 R35 R36 R37 R38 R40: library part CMP-0026852-3, "RES, 1.0 k, 5%, 0.063 W, AEC-Q200 Grade 0, 0402", Manufacturer=Vishay-Dale, Power_W=63mW, Supplier Part Number 1=541-1.0KJCT-ND, TempCo="200 ppm/C", Tolerance_%=5%, Value2=0.063W, Value_Code=1k00, ValueDisplayed=1.0k
R34: library part CMP-0025945-3, "RES, 10 k, 5%, 0.1 W, 0603", Manufacturer="Samsung Electro-Mechanics", Power_W=100mW, Supplier Part Number 1=1276-5086-1-ND, TempCo="100 ppm/C", Tolerance_%=5%, Value2=0.1W, Value_Code=10k0, ValueDisplayed=10k
R39 R41: library part CMP-0018756-2, "RES, 0, 5%, 0.25 W, 1206", Manufacturer=Rohm, Power_W=250mW, Supplier Part Number 1=RHM0.0ECT-ND, TempCo="200 ppm/C", Tolerance_%=5%, Value2=0.25W, Value_Code=0000, ValueDisplayed=0
R42: library part CMP-0026946-3, "RES, 51, 5%, 0.063 W, AEC-Q200 Grade 0, 0402", Manufacturer=Vishay-Dale, Power_W=63mW, Supplier Part Number 1=541-51JCT-ND, TempCo="200 ppm/C", Tolerance_%=5%, Value2=0.063W, Value_Code=51R0, ValueDisplayed=51
R43: library part CMP-0026849-3, "RES, 180, 5%, 0.063 W, AEC-Q200 Grade 0, 0402", Manufacturer=Vishay-Dale, Power_W=63mW, Supplier Part Number 1=541-180JCT-ND, TempCo="200 ppm/C", Tolerance_%=5%, Value2=0.063W, Value_Code=180R, ValueDisplayed=180
T1: library part CMP-0030123-1, "Line Filter", Manufacturer=Bourns, Supplier Part Number 1=SRF0905-472YCT-ND, ValueDisplayed=4.7mH
U1: library part CMP-0080656-1, "Capacitive Touch Sensing Mixed-Signal Microcontroller, RHB0032E (VQFN-32)", Alternate Manufacturer="Texas Instruments"
U2: library part CMP-0043216-2, "Remote 16-Bit I2C and SMBus, Low-Power I/O Expander With Interrupt Output and Config Registers, PW0024A (TSSOP-24)", 5V Tolerant I/O=Yes, Manufacturer="Texas Instruments", Max Frequency(kHz)=400, Operating Temperature Range="-40 to 85 C", Rating=Catalog
U3: library part CMP-0036723-1, "Single Output Fast Transient Response LDO, 1.5 A, Fixed 3.3 V Output, 2.1 to 20 V Input, 6-pin SOT-223 (DCQ), -40 to 125 degC, Green (RoHS & no Sb/Br)", Manufacturer="Texas Instruments"
U6 U9 U13 U16: library part CMP-0043094-3, "Single-Channel ESD in 0402 Package With 10pF Capacitance and 6V Breakdown, DPY0002A (X1SON-2)", Alternate Manufacturer="Texas Instruments", Alternate PartNumber=TPD1E10B06DPYR, Breakdown Voltage(Min)(V)=6, IO Capacitance(Typ)(pF)=10, Operating Temperature Range="-40 to 125 C", Rating=Catalog
ZZ1: library part CMP-0077236-1
ZZ2: library part CMP-0077237-1
ZZ3 ZZ4: library part CMP-0077238-1

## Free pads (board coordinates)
  round 65 smd far side: 1(800,1130) 2(800,1030) 3(800,1330) 4(800,1230)

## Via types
v1: diameter 30, hole 15, Top Layer to Bottom Layer, tented both sides, 102 vias
v2: diameter 20, hole 10, Top Layer to Bottom Layer, tented both sides, 34 vias
v3: diameter 30, hole 20, Top Layer to Bottom Layer, tented both sides, 13 vias
v4: diameter 19.68, hole 7.87, Top Layer to Bottom Layer, 5 vias

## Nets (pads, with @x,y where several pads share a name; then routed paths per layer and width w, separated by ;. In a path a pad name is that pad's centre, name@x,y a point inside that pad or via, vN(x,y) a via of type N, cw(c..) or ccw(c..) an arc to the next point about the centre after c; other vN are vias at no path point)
DETECT: R38.1 U1.7 | length 632.4
  Bottom Layer w8: R38.1@1391.73,1742.13 1430.21,1742.13 1446.85,1725.49 1446.85,1259.84 1476.38,1230.31 U1.7@1539.37,1230.31
FAULT: R37.1 U1.5 | length 365.5
  Bottom Layer w8: R37.1@1391.73,1446.85 1391.73,1255.91 1456.69,1190.95 U1.5@1539.37,1190.95
GND: 1.GND 2.GND 3.GND 4.GND 5.GND 6.GND 7.GND 8.GND C1.2 C2.2 C3.1 C4.2 C5.1 C6.1 C7.1 C8.1 C9.1 C10.2 C12.2 C13.2 C14.2 C15.2 D1.1 D2.1 D3.1 D4.1 D5.1 D6.1 D7.1 D8.1 D9.1 D10.1 D11.1 D12.1 D13.1 D14.1 D15.1 D16.1 D17.1 D18.1 D19.1 D20.1 D22.1 J1.1 J1.2 J1.7 J1.8 J1.19 J1.20 pad.4 Q1.2 R41.2 T1.3 U1.31 U1.33 U2.2 U2.3 U2.12 U2.21 U3.3 U3.6 U6.1 U9.1 U13.1 U16.1 | length 2916.4
  Bottom Layer w10: 366.14,897.64 437.01,897.64 ; 369.09,1150.59 432.09,1150.59 ; 370.08,1001.97 431.1,1001.97 ; 370.08,1196.44 430.53,1196.44 ; 1584.65,1040.26 U1.31@1584.65,1086.61 1584.65,1131.89 v4(1633.86,1181.1)
  Bottom Layer w15: U2.21@1717.52,1950.79 1717.52,2097.24 ; 1937.01,2147.3 1922.24,2162.06 U2.12@1922.24,2183.07 1922.24,2204.59 1937.01,2219.35
  Bottom Layer w16: 1666.34,2128.94 U2.2@1666.34,2183.07 ; 1666.34,2321.21 U2.2@1666.34,2183.07 ; 1691.93,2130.74 U2.3@1691.93,2183.07 ; 1691.93,2433.43 U2.3@1691.93,2183.07 ; U2.2@1666.34,2183.07 U2.3@1691.93,2183.07
  Bottom Layer w20: D22.1@313.98,2263.78 313.98,2390.75 356.66,2433.43 856.3,2433.43 ; U3.6@1141.73,2626.97 v3(1141.73,2509.84) U3.3@1141.73,2392.72 1141.73,2284.09 ccw(c1152.2,2284.09) 1152.2,2273.62 1190.94,2273.62 v3(1220.47,2244.09) ; C4.2@1933.07,1190.94 v3(1978.35,1190.94)
  Bottom Layer w40: C14.2@1555.91,2411.42 T1.3@1555.91,2765.75 1555.91,2820.81 cw(c1591.4,2820.81) 1591.4,2856.3 R41.2@1702.76,2856.3
  other v1: 1884.45,149.37 1127.96,160.28 4498.03,167.32 3661.42,182.87 2214.57,187.01 2854.33,187.01 299.21,188.27 5246.06,209.8 1663.39,295.28 2942.69,364.17 1909.45,374.02 3741.03,374.02 4526.59,374.02 2042.77,394.96 1477.64,421.26 866.14,429.13 2214.57,455.7 2893.7,501.27 1157.48,507.87 4478.35,546.42 1734.27,551.18 1909.45,570.87 3740.16,590.55 5236.22,645.17 507.87,661.42 763.78,665.35 2893.7,682.29 4472.08,687.98 807.09,834.65 1998.03,846.46 3665.37,903.13 2669.3,910.43 1378.05,913.83 1899.61,925.2 1083.25,931.83 1444.88,937.01 2266.01,944.57 4468.5,964.57 1594.49,1019.68 5236.22,1033.46 401.57,1051.18 578.74,1072.83 4491.51,1102.36 2942.91,1178.53 3665.37,1185.38 4488.19,1338.58 2942.91,1359.55 5226.38,1368.11 1020.67,1407.48 3665.37,1446.33 2849.58,1452.76 1850.39,1486.22 4509.51,1500 2005.48,1527.56 886.1,1545.28 602.36,1551.18 958.04,1677.52 2716.54,1681.75 3481.31,1722.44 649.61,1744.09 4206.28,1749.59 4974.61,1751.97 1520.28,1783.46 377.49,1848.43 2893.7,1951.82 3661.42,1993.06 4498.03,1998.03 5220.68,1998.03 598.43,2000 1099.45,2057.09 1858.27,2057.09 1998.03,2066.93 1751.97,2085.34 866.14,2116.14 1402.46,2117.58 4498.03,2180.48 3717.07,2214.57 2893.7,2216.64 1988.19,2266.95 5216.54,2332.68 3524.95,2490.16 2712.48,2495.08 4458.66,2538.58 5230.83,2687.01 2895.44,2765.75 4498.03,2785.43 3729.84,2942.91 5231.41,3021.65 2893.7,3035.54 3488.35,3257.87 5218.38,3289.24 4478.35,3292.02 2165.35,3293.22 2716.54,3305.61
  other v3: 1550.86,2291.34 934.07,2362.2 1657.82,2458.36 855.95,2490.16 1649.61,2564.36 1801.18,2602.36 1968.5,2641.73
  other v4: 1633.86,1123.03 1575.79,1181.1 1691.93,1181.1 1633.86,1239.17
LED0: D1.2 R17.2 | length 73.8
  Bottom Layer w8: R17.2@2346.46,3248.03 D1.2@2420.28,3248.03
LED1: D2.2 R19.2 | length 75.8
  Bottom Layer w8: R19.2@3131.89,3248.03 D2.2@3207.68,3248.03
LED2: D3.2 R20.2 | length 75
  Bottom Layer w8: R20.2@3920.05,3248.03 D3.2@3995.08,3248.03
LED3: D4.2 R21.2 | length 73.8
  Bottom Layer w8: R21.2@4708.66,3248.03 D4.2@4782.48,3248.03
LED4: D5.2 R22.2 | length 73.8
  Bottom Layer w8: R22.2@2346.46,2460.63 D5.2@2420.28,2460.63
LED5: D6.2 R23.2 | length 73.8
  Bottom Layer w8: R23.2@3133.86,2460.63 D6.2@3207.68,2460.63
LED6: D7.2 R24.2 | length 75
  Bottom Layer w8: R24.2@3920.05,2460.63 D7.2@3995.08,2460.63
LED7: D8.2 R25.2 | length 73.8
  Bottom Layer w8: R25.2@4708.66,2460.63 D8.2@4782.48,2460.63
LED8: D9.2 R26.2 | length 74
  Bottom Layer w8: R26.2@2346.26,1673.23 D9.2@2420.28,1673.23
LED9: D10.2 R27.2 | length 73.8
  Bottom Layer w8: R27.2@3133.86,1673.23 D10.2@3207.68,1673.23
LED10: D11.2 R29.2 | length 73.8
  Bottom Layer w8: R29.2@3921.26,1673.23 D11.2@3995.08,1673.23
LED11: D12.2 R30.2 | length 73.8
  Bottom Layer w8: R30.2@4708.66,1673.23 D12.2@4782.48,1673.23
LED12: D13.2 R31.2 | length 73.8
  Bottom Layer w8: R31.2@2346.46,885.83 D13.2@2420.28,885.83
LED13: D14.2 R32.2 | length 73.8
  Bottom Layer w8: R32.2@3133.86,885.83 D14.2@3207.68,885.83
LED14: D15.2 R33.2 | length 75
  Bottom Layer w8: R33.2@3920.05,885.83 D15.2@3995.08,885.83
LED15: D16.2 R35.2 | length 73.8
  Bottom Layer w8: R35.2@4708.66,885.83 D16.2@4782.48,885.83
NetC11_1: C11.1 D21.1 JP2.1 JP2.2 R41.1 T1.2 | length 2229.1
  Bottom Layer w20: T1.2@1555.12,3060.24 T1.2@1555.91,3061.02 T1.2@1562.99,3068.11
  Bottom Layer w40: JP2.1@108.27,3228.35 JP2.2@836.61,3228.35 836.61,3152.36 ccw(c894.49,3152.36) 894.49,3094.48 978.35,3094.49 ccw(c978.35,3149.61) 1033.46,3149.61 1033.46,3263.29 cw(c1096.94,3263.29) 1096.94,3326.77 1513.78,3326.77 ; 1515.75,3326.77 1513.78,3326.77 ; T1.2@1555.12,3060.24 1555.12,3190.94 C11.1@1562.99,3198.82 1562.99,3277.56 ccw(c1513.78,3277.56) 1513.78,3326.77 ; T1.2@1555.91,3061.02 1555.91,3005.96 ccw(c1591.4,3005.96) 1591.4,2970.47 R41.1@1702.76,2970.47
